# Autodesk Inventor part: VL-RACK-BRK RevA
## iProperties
Created: 2007-10
Part Number: VL-RACK-BRK RevA
Material: Steel
Document SubType Name: Modeling
Density: 7.85 g/cm^3
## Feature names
1. Base1
